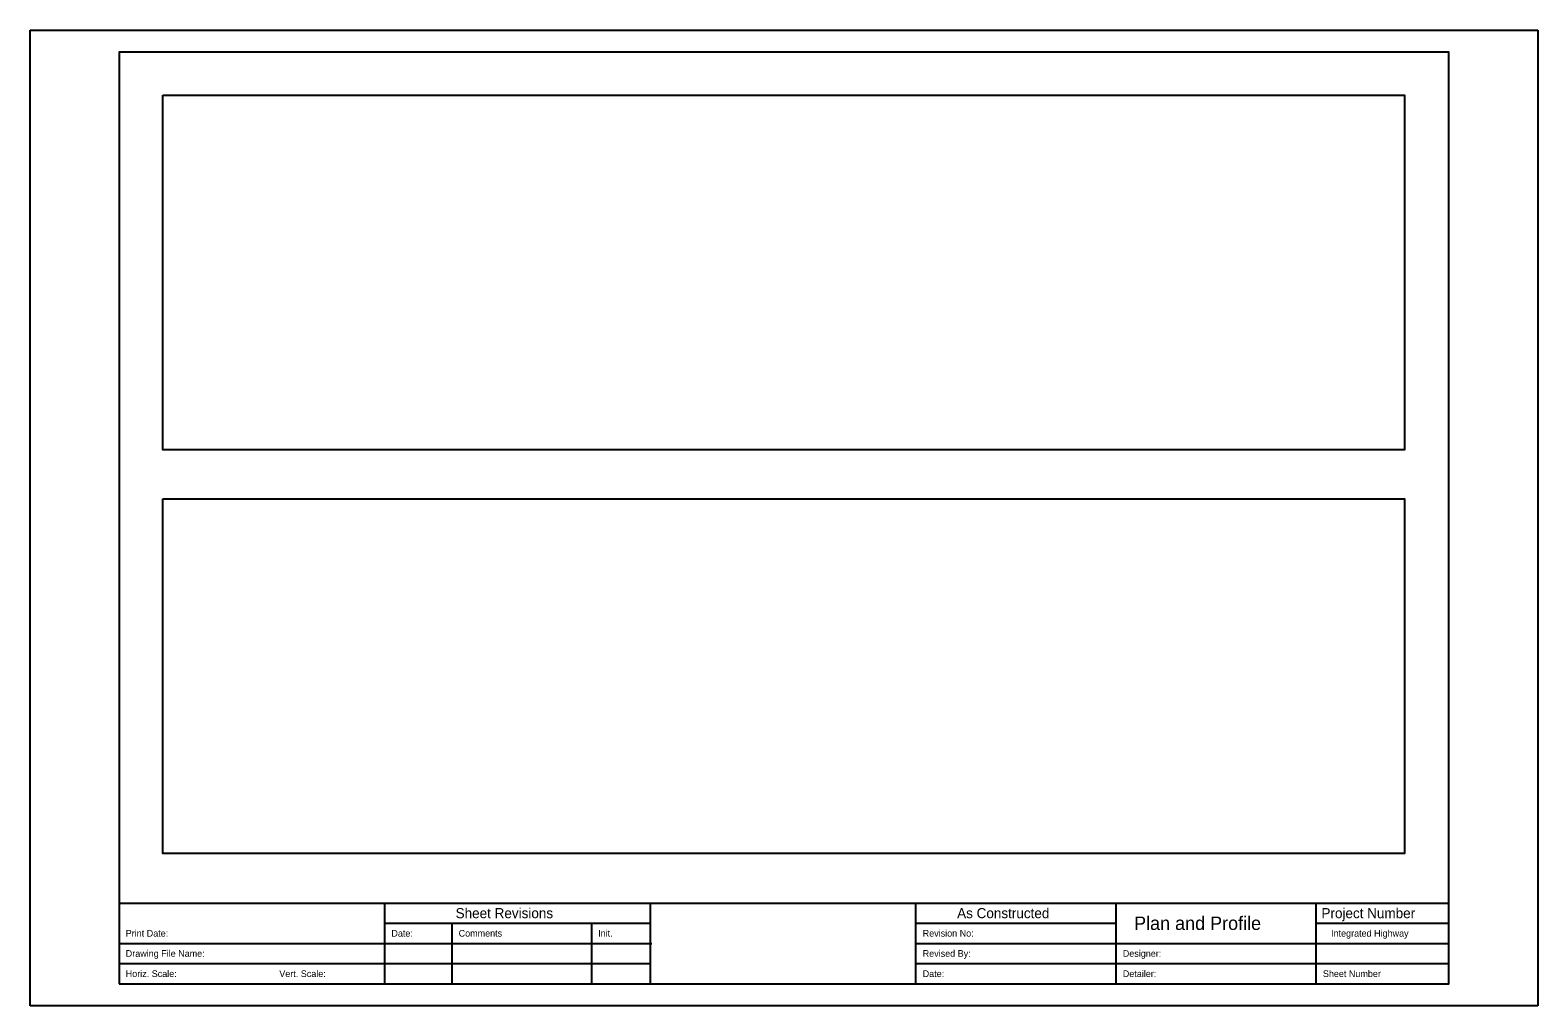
# Model space of a CAD drawing. Extents: x 0 to 2.83, y 0 to 1.83.
import ezdxf

# ---------------------------------------------------------------- set-up
doc = ezdxf.new("R2010")
doc.units = 0
for name, color, linetype in [('Constructions', 7, 'Continuous'), ('Default', 7, 'Continuous'), ('Draft_Sheet', 7, 'Continuous')]:
    doc.layers.add(name, color=color, linetype=linetype)

msp = doc.modelspace()

# ---------------------------------------------------------------- linework, layer by layer
at = {"layer": 'Constructions'}
for points in [[(0.2492, 1.7114), (2.5826, 1.7114), (2.5826, 1.0447), (0.2492, 1.0447)], [(0.2492, 0.9526), (2.5826, 0.9526), (2.5826, 0.286), (0.2492, 0.286)]]:
    msp.add_lwpolyline(points, close=True, dxfattribs=at)
at = {"layer": 'Default'}
for p, q in [((0, 1.8333), (2.8331, 1.8333)), ((0, 0), (0, 1.8333)), ((2.8331, 1.8333), (2.8331, 0)), ((2.8331, 0), (0, 0))]:
    msp.add_line(p, q, dxfattribs=at)
at = {"layer": 'Draft_Sheet'}
for p, q in [((0.167, 0.1932), (2.6661, 0.1932)), ((0.6662, 0.0415), (0.6662, 0.1932)), ((1.1654, 0.0415), (1.1654, 0.1932)), ((1.6646, 0.0415), (1.6646, 0.1932)), ((2.0406, 0.0415), (2.0406, 0.1932)), ((2.4165, 0.0415), (2.4165, 0.1932)), ((0.6662, 0.1552), (1.1654, 0.1552)), ((0.7926, 0.1552), (0.7926, 0.0415)), ((1.0548, 0.1552), (1.0548, 0.0415)), ((1.6646, 0.1552), (2.0406, 0.1552)), ((2.4165, 0.1552), (2.6661, 0.1552)), ((0.167, 0.1173), (1.1685, 0.1173)), ((1.6646, 0.1173), (2.6661, 0.1173)), ((0.167, 0.0794), (1.1654, 0.0794)), ((1.6646, 0.0794), (2.6661, 0.0794))]:
    msp.add_line(p, q, dxfattribs=at)
msp.add_lwpolyline([(0.167, 0.0415), (2.6661, 0.0415), (2.6661, 1.7918), (0.167, 1.7918)], close=True, dxfattribs=at)

# ---------------------------------------------------------------- texts
for s, height, p in [('Sheet Revisions', 0.018957, (0.7995, 0.1647)), ('As Constructed', 0.018957, (1.7419, 0.1647)), ('Project Number', 0.018957, (2.4265, 0.1647)), ('Print Date:', 0.012638, (0.1796, 0.13)), ('Date:', 0.01264, (0.6788, 0.13)), ('Comments', 0.01264, (0.8052, 0.13)), ('Init.', 0.01264, (1.0674, 0.13)), ('Revision No:', 0.012638, (1.6772, 0.13)), ('Plan and Profile', 0.025276, (2.0744, 0.1426)), ('Integrated Highway', 0.012638, (2.4446, 0.13)), ('Drawing File Name:', 0.012638, (0.1796, 0.0921)), ('Revised By:', 0.012638, (1.6772, 0.0921)), ('Designer:', 0.01264, (2.0532, 0.0921)), ('Horiz. Scale:', 0.012638, (0.1796, 0.0541)), ('Vert. Scale:', 0.012638, (0.4682, 0.0541)), ('Date:', 0.01264, (1.6772, 0.0541)), ('Detailer:', 0.01264, (2.0532, 0.0541)), ('Sheet Number', 0.012638, (2.4292, 0.0541))]:
    msp.add_text(s, height=height, dxfattribs=at).set_placement(p)

doc.saveas('drawing.dxf')
